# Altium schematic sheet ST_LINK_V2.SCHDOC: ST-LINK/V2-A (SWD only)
size A4; DocumentNumber: 3; Revision: D.1(PCB.SCH); SheetNumber: 3; SheetTotal: 7
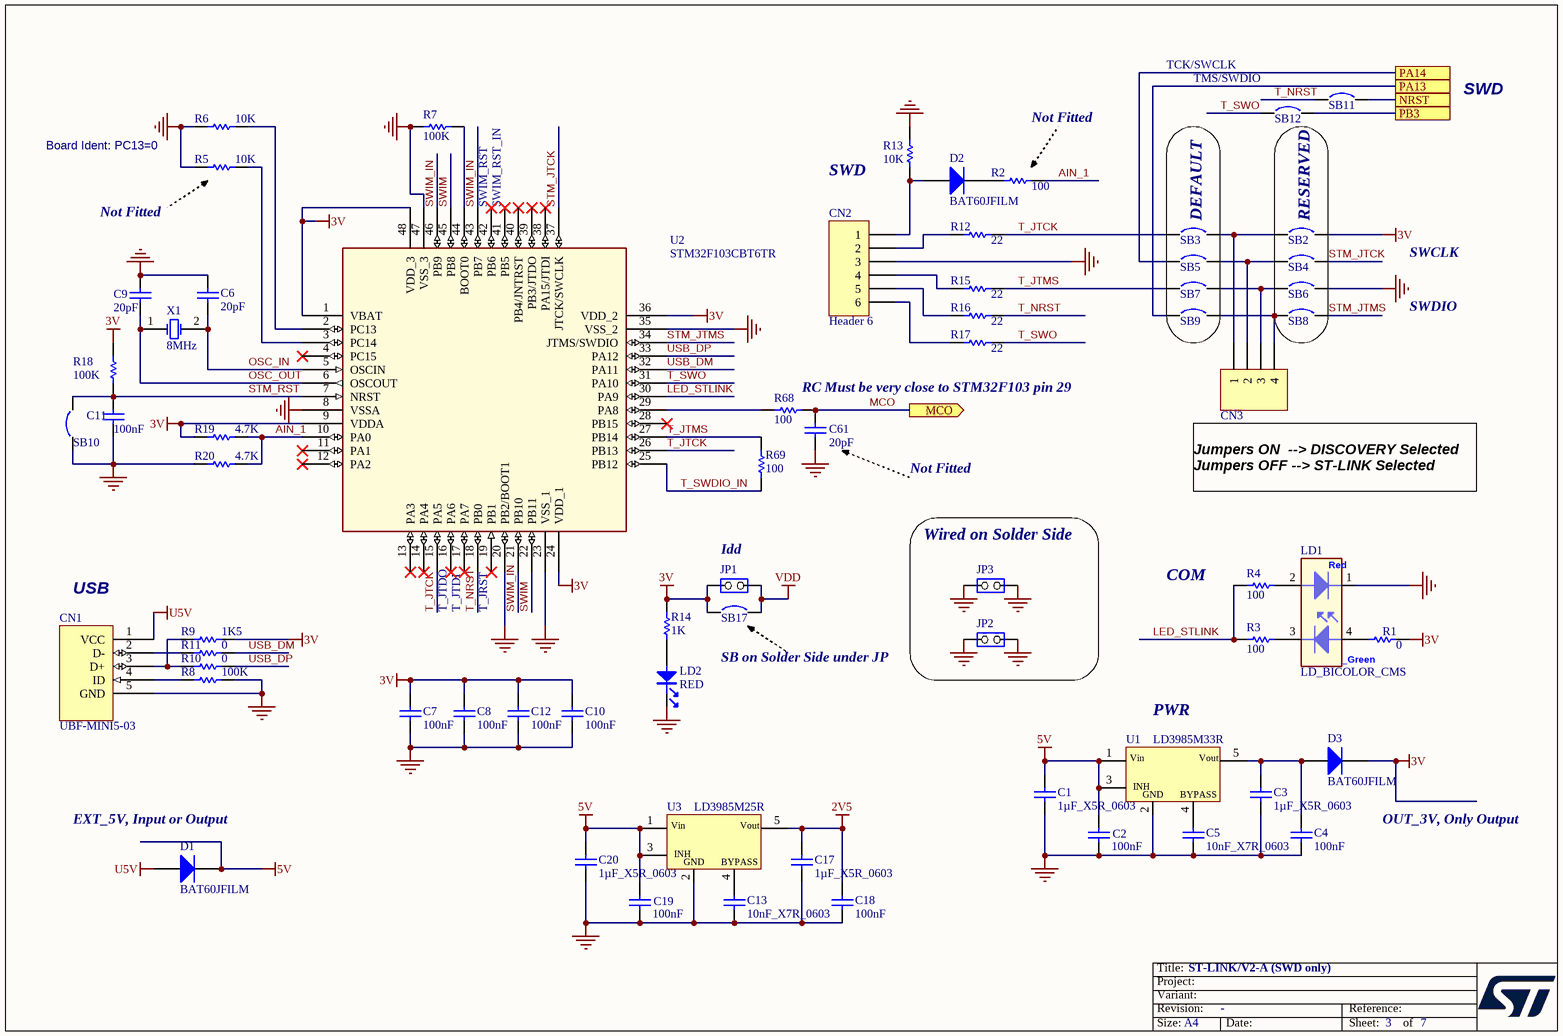
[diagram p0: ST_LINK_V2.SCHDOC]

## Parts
C1  1µF_X5R_0603  [0603C]
C2  100nF  [0402C]
C3  1µF_X5R_0603  [0603C]
C4  100nF  [0402C]
C5  10nF_X7R_0603  [0603C]
C6  20pF  [0402C]
C7  100nF  [0402C]
C8  100nF  [0402C]
C9  20pF  [0402C]
C10  100nF  [0402C]
C11  100nF  [0402C]
C12  100nF  [0402C]
C13  10nF_X7R_0603  [0603C]
C17  1µF_X5R_0603  [0603C]
C18  100nF  [0402C]
C19  100nF  [0402C]
C20  1µF_X5R_0603  [0603C]
C61  20pF  [0603C]
CN1  UBF-MINI5-03  [USB-MINI-B-SMD-A_]
CN2  Header 6  [HEADER6$2F$2.54]
CN3  Header 4  [HEADER4$2F$2.54]  (value not drawn)
D1  BAT60JFILM  [SOD323$2F$A]
D2  BAT60JFILM  [SOD323$2F$A]
D3  BAT60JFILM  [SOD323$2F$A]
JP1  (no value)  [SIP2$2F$2.54]
JP2  (no value)  [SIP2$2F$2.54]
JP3  (no value)  [SIP2$2F$2.54]
LD1  LD_BICOLOR_CMS  [AV02-0501EN]
LD2  RED  [LED0603]
R1  0  [0603R]
R2  100  [0402R]
R3  100  [0402R]
R4  100  [0402R]
R5  10K  [0402R]
R6  10K  [0402R]
R7  100K  [0402R]
R8  100K  [0402R]
R9  1K5  [0402R]
R10  0  [0603R]
R11  0  [0603R]
R12  22  [0402R]
R13  10K  [0402R]
R14  1K  [0402R]
R15  22  [0402R]
R16  22  [0402R]
R17  22  [0402R]
R18  100K  [0402R]
R19  4.7K  [0402R]
R20  4.7K  [0402R]
R68  100  [0603R]
R69  100  [0402R]
SB2  Circuit Breaker  [JUMPER]  (value not drawn)
SB3  Circuit Breaker  [JUMPER]  (value not drawn)
SB4  Circuit Breaker  [JUMPER]  (value not drawn)
SB5  Circuit Breaker  [JUMPER]  (value not drawn)
SB6  Circuit Breaker  [JUMPER]  (value not drawn)
SB7  Circuit Breaker  [JUMPER]  (value not drawn)
SB8  Circuit Breaker  [JUMPER]  (value not drawn)
SB9  Circuit Breaker  [JUMPER]  (value not drawn)
SB10  Circuit Breaker  [JUMPER]  (value not drawn)
SB11  Circuit Breaker  [JUMPER]  (value not drawn)
SB12  Circuit Breaker  [JUMPER]  (value not drawn)
SB17  Circuit Breaker  [JUMPER]  (value not drawn)
U1  LD3985M33R  [SOT-23-5L]
U2  STM32F103CBT6TR  [LQFP48$2F$0.5MM$5C$9X9B]
U3  LD3985M25R  [SOT-23-5L]
X1  8MHz  [HC-49A]

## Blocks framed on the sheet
DEFAULT: SB3 SB5 SB7 SB9
RESERVED: SB2 SB4 SB6 SB8
Wired on Solder Side: JP2 JP3

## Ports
MCO (out), NRST, PA13, PA14, PB3

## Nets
2V5: C17.1 C18.2 U3.5(Vout)
3V: C7.2 C8.2 C10.2 C12.1 D3.2(K) JP1.1(COMMON) R1.2 R9.2 R14.2 R18.2 R19.1 SB2.2 SB17.1 U2.1(VBAT) U2.9(VDDA) U2.24(VDD_1) U2.36(VDD_2) U2.48(VDD_3)
5V: C1.2 C2.2 C19.2 C20.2 D1.2(K) U1.1(Vin) U1.3(CE) U3.1(Vin) U3.3(CE)
GND: C1.1 C2.1 C3.2 C4.1 C5.1 C6.1 C7.1 C8.1 C9.1 C10.1 C11.1 C12.2 C13.1 C17.2 C18.1 C19.1 C20.1 C61.2 CN1.5(GND) CN2.3 JP2.1(COMMON) JP2.2(NO) JP3.1(COMMON) JP3.2(NO) LD1.1 LD2.2 R5.1 R6.1 R7.1 R8.2 R13.2 R20.1 SB6.2 SB10.1 U1.2(GND) U2.8(VSSA) U2.20(PB2/BOOT1) U2.23(VSS_1) U2.35(VSS_2) U2.47(VSS_3) U3.2(GND)
U5V: CN1.1(VCC) D1.1(A)
VDD: JP1.2(NO) SB17.2
AIN_1: R2.2 R19.2 R20.2 U2.10(PA0)
LED_STLINK: R3.1 R4.1 U2.30(PA9)
MCO: C61.1 R68.2 ; port MCO
NRST: SB11.2 ; port NRST
OSC_IN: C6.2 U2.5(OSCIN) X1.2(OSC2)
OSC_OUT: C9.2 U2.6(OSCOUT) X1.1(OSC1)
PA13: SB9.1 ; port PA13
PA14: SB5.1 ; port PA14
PB3: SB12.2 ; port PB3
STM_JTCK: SB4.2 U2.37(JTCK/SWCLK)
STM_JTMS: SB8.2 U2.34(JTMS/SWDIO)
STM_RST: C11.2 R18.1 SB10.2 U2.7(NRST)
SWIM: U2.22(PB11) U2.45(PB8)
SWIM_IN: U2.21(PB10) U2.43(PB7) U2.46(PB9)
T_JTCK: R12.2 SB3.1 U2.15(PA5) U2.26(PB13)
T_JTMS: R15.2 R69.2 SB7.1 U2.27(PB14)
T_NRST: R16.2 SB11.1 U2.18(PB0)
T_SWDIO_IN: R69.1 U2.25(PB12)
T_SWO: R17.2 SB12.1 U2.31(PA10)
USB_DM: R11.2 U2.32(PA11)
USB_DP: R10.2 U2.33(PA12)
NetC3_1: C3.1 C4.2 D3.1(A) U1.5(Vout)
NetC5_2: C5.2 U1.4(BYPASS)
NetC13_2: C13.2 U3.4(BYPASS)
NetCN1_2: CN1.2(D-) R11.1
NetCN1_3: CN1.3(D+) R9.1 R10.1
NetCN1_4: CN1.4(ID) R8.1
NetCN2_1: CN2.1 D2.1(A) R13.1
NetCN2_2: CN2.2 R12.1
NetCN2_4: CN2.4 R15.1
NetCN2_5: CN2.5 R16.1
NetCN2_6: CN2.6 R17.1
NetCN3_1: CN3.1 SB2.1 SB3.2
NetCN3_2: CN3.2 SB4.1 SB5.2
NetCN3_3: CN3.3 SB6.1 SB7.2
NetCN3_4: CN3.4 SB8.1 SB9.2
NetD2_2: D2.2(K) R2.1
NetLD1_2: LD1.2 R4.2
NetLD1_3: LD1.3 R3.2
NetLD1_4: LD1.4 R1.1
NetLD2_1: LD2.1 R14.1
NetR5_2: R5.2 U2.3(PC14)
NetR6_2: R6.2 U2.2(PC13)
NetR7_2: R7.2 U2.44(BOOT0)
NetR68_1: R68.1 U2.29(PA8)

Not connected (* = marked no-connect by the designer): U2 4(PC15)* 11(PA1)* 12(PA2)* 13(PA3)* 14(PA4)* 16(PA6)* 17(PA7)* 19(PB1)* 28(PB15)* 38(PA15/JTDI)* 39(PB3/JTDO)* 40(PB4/JNTRST)* 41(PB5)* 42(PB6)*

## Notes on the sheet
- TCK/SWCLK
- (near SB12) TMS/SWDIO
- SWD
- Board Ident: PC13=0
- Not Fitted
- SWIM_RST
- SWIM_RST_IN
- SWCLK
- SWDIO
- (near R68) RC Must be very close to STM32F103 pin 29
- Jumpers ON  --> DISCOVERY Selected
  Jumpers OFF --> ST-LINK Selected
- (near JP1) Idd
- COM
- (near CN1) USB
- (near U2) T_JTDO
- (near U2) T_JTDI
- (near U2) T_JRST
- SB on Solder Side under JP
- (near U1) PWR
- (near D1) EXT_5V, Input or Output
- OUT_3V, Only Output

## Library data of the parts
C1 C3 C17 C20 = CAP SMD 0603  X5R 1µF 25V 10%: 0603  X5R 1µF; Manuf_1: YAGEO; Manuf_Part_1: CC0603KRX5R7BB105; Value: 1uF; Rated voltage: 25V; Tolerance: 10%
C2 C4 C7 C8 C10-C12 C18 C19 = Cap: Capacitor; Manuf_Part_1: CC0402KRX7R7BB104; Manuf_1: YAGEO
C5 C13 = CAP SMD 0603  X7R 10000PF 50V 10%: 0603  X7R 10NF; Manuf_1: YAGEO; Manuf_Part_1: CC0603KRX7R9BB103; Order code RS: 2040779; Rated voltage: 50V; Tolerance: 10%
C6 C9 = Cap: Capacitor; Manuf_Part_1: CC0402JRNPO9BN200; Manuf_1: YAGEO
C61 = Cap: Capacitor; Fitted: NO
CN1 = USB-MINI-typeB connector_: Manuf_1: MTCONN
CN2 = Header 6: Header, 6-Pin; Manuf_Part_1: 313106S141116; Manuf_1: LYCN
CN3 = Header 4: Header, 4-Pin; Manuf_1: LYCN; Manuf_Part_1: 313104S141116
D1-D3 = BAT60JFILM: Manuf_1: STM; Code - JEDEC: DO-214-AB; Provided: ST
JP1 = JP2: Manuf_Part_1: 313102S141116; Manuf_1: LYCN
JP2 JP3 = JP2: Manuf_1: LYCN; Manuf_Part_1: 313102S141145
LD1 = LD_BICOLOR_CMS: Bicolor Led; Manuf_Part_1: HSMF-A201-A00J1; Manuf_1: Avago Technologies; Ref St: xxxxxx; cap_dec: ----
LD2 = PHOTO: Manuf_Part_1: 19-213-R6C-AP1Q2B-3T; Manuf_1: EVERLIGHT
R1 R10 R11 = res1: Resistor; Manuf_Part_1: RC0603JR-070RL; Manuf_1: YAGEO
R2 = res1: Resistor; Fitted: NO
R3 R4 R69 = res1: Resistor; Manuf_Part_1: RC0402FR-07100RL; Manuf_1: YAGEO
R5 = res1: Resistor; Manuf_Part_1: RC0402FR-0710KL; Manuf_1: YAGEO; Fitted: NO
R6 R13 = res1: Resistor; Manuf_Part_1: RC0402FR-0710KL; Manuf_1: YAGEO
R7 R8 R18 = res1: Resistor; Manuf_Part_1: RC0402FR-07100KL; Manuf_1: YAGEO
R9 = res1: Resistor; Manuf_Part_1: RC0402FR-071K5L; Manuf_1: YAGEO
R12 R15-R17 = res1: Resistor; Manuf_Part_1: RC0402FR-0722RL; Manuf_1: YAGEO
R14 = res1: Resistor; Manuf_Part_1: RC0402FR-071KL; Manuf_1: YAGEO
R19 R20 = res1: Resistor; Manuf_Part_1: RC0402FR-074K7L; Manuf_1: YAGEO
R68 = res1: Resistor; Manuf_Part_1: RC0603FR-07100RL; Manuf_1: YAGEO
SB2 SB4 SB6 SB8 SB10 SB17 = Circuit Breaker: Solder: NO
SB3 SB5 SB7 SB9 SB11 SB12 = Circuit Breaker: Solder: YES
U1 = LD3985M33R: Ultra low drop-low noise BiCMOS voltage, regulators low ESR capacitors compatible; Manuf_1: STM; Provided: ST
U2 = STM32F103CBT6: Medium-density performance line ARM-based 32-bit MCU with 128KB Flash; Manuf_1: STM; Ref St: xxxxxxxx; Provided: ST; ECCN_US/EU: 3A991A2/NEC
U3 = LD3985M25R: Ultra low drop-low noise BiCMOS voltage, regulators low ESR capacitors compatible; Manuf_1: STM; Provided: ST
X1 = XTAL: Crystal Oscillator; Manuf_Part_1: HC-49S-C20QSA-8.000MHZ; Manuf_1: jfvny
